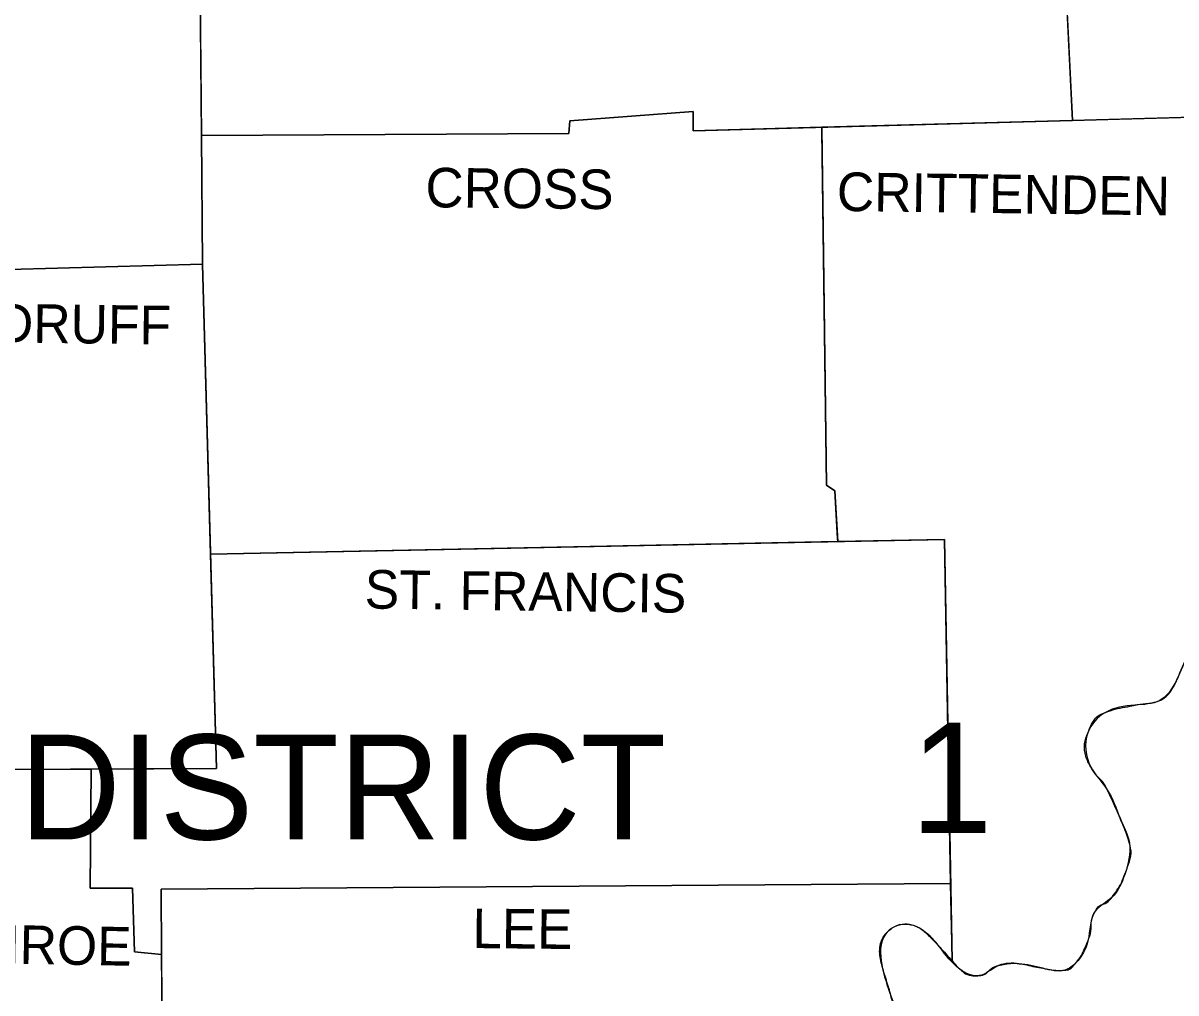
# Model space of a CAD drawing. Extents: x 185 to 5012, y 113 to 2127.
# Drawn here: x 3121.8 to 3244.3, y 1737.5 to 1840.7 of the extents above; entities that cross this region are included whole.
import ezdxf

# ---------------------------------------------------------------- set-up
doc = ezdxf.new("R2010")
doc.units = 0
doc.layers.add('Default', color=7, linetype='Continuous')
doc.layers.add('R_No Plot', color=7, linetype='Continuous')

msp = doc.modelspace()

# ---------------------------------------------------------------- linework, layer by layer
at = {"layer": 'Default'}
for points in [[(3094.0589629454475, 1986.3640190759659), (3093.688561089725, 1983.4007516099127), (3095.6453774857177, 1983.1072483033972), (3095.547585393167, 1981.9330851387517), (3097.797853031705, 1981.4438754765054), (3097.9935871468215, 1979.8784120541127), (3099.0698249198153, 1979.1934960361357), (3099.3633136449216, 1974.4970308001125), (3104.940236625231, 1973.9099492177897), (3104.940236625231, 1969.7026936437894), (3106.9948825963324, 1969.409152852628), (3106.9948825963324, 1967.7458549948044), (3108.7560398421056, 1967.2566453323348), (3108.6582102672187, 1961.5817232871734), (3110.2236333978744, 1961.2882199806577), (3110.615026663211, 1948.4707469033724), (3102.298538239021, 1947.687996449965), (3102.3963678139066, 1944.9483698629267), (3099.8524990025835, 1944.850572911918), (3100.7331151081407, 1894.3635060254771), (3140.162894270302, 1893.4829211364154), (3140.847776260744, 1815.0127317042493), (3115.1156743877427, 1814.3278156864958), (3114.604746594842, 1828.1237080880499)], [(3229.6643301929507, 1913.337334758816), (3231.3504033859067, 1870.3919701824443), (3233.3396171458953, 1830.3091142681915)], [(3140.7282791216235, 1828.704087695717), (3179.7883700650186, 1828.9064585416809), (3179.8862371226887, 1830.2762530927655), (3192.9968619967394, 1831.2546724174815), (3192.9968619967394, 1829.199999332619), (3251.279533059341, 1830.8023237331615)], [(3206.689650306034, 1829.5764455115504), (3207.1837621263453, 1791.5303680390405), (3208.064340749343, 1790.9433614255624), (3208.376644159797, 1785.5293148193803)], [(3206.6945392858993, 1829.199999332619), (3207.1837621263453, 1791.5303680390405), (3208.064340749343, 1790.9433614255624), (3208.3578294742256, 1785.8554834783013)], [(3206.6945392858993, 1829.199999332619), (3207.1837621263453, 1791.5303680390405), (3208.064340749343, 1790.9433614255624), (3208.3578294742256, 1785.8554834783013)], [(3206.6945392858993, 1829.199999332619), (3207.1837621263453, 1791.5303680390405), (3208.064340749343, 1790.9433614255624), (3208.3578294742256, 1785.8554834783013)], [(3206.6945392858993, 1829.199999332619), (3207.1837621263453, 1791.5303680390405), (3208.064340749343, 1790.9433614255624), (3208.3578294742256, 1785.8554834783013)], [(3140.847776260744, 1815.0127317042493), (3142.3154072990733, 1761.3947004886), (3119.029307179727, 1761.296866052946), (3118.931477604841, 1759.1443210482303), (3112.1804872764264, 1758.7529458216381), (3111.593397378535, 1747.598845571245), (3102.3153265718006, 1747.598845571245)], [(3141.6915784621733, 1784.1854927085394), (3219.707372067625, 1785.7576490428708)], [(3219.707372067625, 1785.7576490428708), (3220.490046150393, 1742.9023428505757)], [(3219.707372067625, 1785.7576490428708), (3220.490046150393, 1742.9023428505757)], [(3219.707372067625, 1785.7576490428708), (3220.490046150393, 1742.9023428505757)], [(3219.707372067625, 1785.7576490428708), (3220.490046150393, 1742.9023428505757)], [(3219.707372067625, 1785.7576490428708), (3220.490046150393, 1742.9023428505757)], [(3219.707372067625, 1785.7576490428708), (3220.490046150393, 1742.9023428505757)], [(3219.707372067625, 1785.7576490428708), (3220.490046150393, 1742.9023428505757)], [(3219.707372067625, 1785.7576490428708), (3220.5258742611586, 1740.9405752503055)], [(3129.0133703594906, 1761.3388131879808), (3128.9112187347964, 1748.6750993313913), (3133.411866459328, 1748.6750993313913), (3133.6076005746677, 1741.9239235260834), (3136.4970377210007, 1741.6249948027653)], [(3140.5253881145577, 1661.792305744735), (3149.653450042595, 1662.3774428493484), (3149.5555829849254, 1682.2395575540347), (3142.4132368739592, 1682.728842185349), (3142.8045926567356, 1721.572524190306), (3136.6406547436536, 1722.4531090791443), (3136.444958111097, 1748.5772648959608), (3220.375622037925, 1749.1676331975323)]]:
    msp.add_lwpolyline(points, dxfattribs=at)
msp.add_spline([(3256.2019266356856, 1822.4487860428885), (3256.5932824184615, 1819.6113625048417), (3254.929992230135, 1816.5782326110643), (3254.3429772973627, 1813.5451027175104), (3254.63646602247, 1810.5119353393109), (3251.505582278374, 1808.8485999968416), (3248.7660543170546, 1806.891761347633), (3250.33151493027, 1804.5435099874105), (3253.2667020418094, 1802.3909649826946), (3256.2019266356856, 1800.727667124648), (3258.0609134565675, 1799.0642942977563), (3258.550098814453, 1795.052707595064), (3259.0393216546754, 1792.508787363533), (3260.01772985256, 1788.9864478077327), (3260.409085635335, 1786.5403994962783), (3258.64792838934, 1783.6050665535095), (3256.5932824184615, 1783.0180224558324), (3254.4408068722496, 1783.7029009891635), (3251.896938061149, 1783.8986073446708), (3249.842292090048, 1781.9417686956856), (3248.374661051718, 1779.2021421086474), (3246.907067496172, 1776.462515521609), (3245.830829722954, 1774.114339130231), (3244.7545544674, 1771.5703814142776), (3242.602078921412, 1768.635048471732), (3239.9604180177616, 1768.145876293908), (3236.829459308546, 1767.3631258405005), (3234.9705099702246, 1765.210580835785), (3235.2640361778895, 1761.590369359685), (3237.0251559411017, 1759.1443210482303), (3238.394957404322, 1756.1111911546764), (3239.3733281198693, 1753.4693615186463), (3238.884105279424, 1750.1427283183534), (3237.5143787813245, 1747.696680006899), (3235.753184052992, 1746.2290135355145), (3234.9705099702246, 1743.0980492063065), (3233.6985755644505, 1740.7497978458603), (3232.524470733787, 1739.9670473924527), (3230.1762985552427, 1740.1627537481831), (3227.6324297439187, 1740.6519634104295), (3225.479954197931, 1740.4562195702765), (3223.4253082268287, 1739.37996581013), (3221.370662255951, 1740.0648818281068), (3219.2181867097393, 1742.4131331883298), (3217.4569919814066, 1744.174302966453), (3215.500213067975, 1744.8591814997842), (3213.445567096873, 1743.7829277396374), (3213.0542113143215, 1740.5541289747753), (3214.032619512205, 1737.22745829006), (3214.913160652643, 1732.7266994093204), (3214.032619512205, 1729.9870728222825), (3213.739093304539, 1725.486276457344)], degree=3, dxfattribs=at)
at = {"layer": 'R_No Plot'}
for p, q in [((3233.3396171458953, 1830.3091142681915), (3231.3504033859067, 1870.3919701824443)), ((3140.3825345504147, 1868.3176888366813), (3140.7282791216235, 1828.704087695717)), ((3233.3396171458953, 1830.3091142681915), (3251.279533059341, 1830.8023237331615)), ((3140.7282791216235, 1828.704087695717), (3140.847776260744, 1815.0127317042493)), ((3206.689650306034, 1829.5764455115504), (3206.6945392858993, 1829.199999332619)), ((3206.6945392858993, 1829.199999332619), (3206.689656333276, 1829.5759814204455)), ((3206.6945392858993, 1829.199999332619), (3207.1837621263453, 1791.5303680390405)), ((3207.1837621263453, 1791.5303680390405), (3206.6945392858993, 1829.199999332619)), ((3140.847776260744, 1815.0127317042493), (3141.6915784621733, 1784.1854927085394)), ((3141.6915784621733, 1784.1854927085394), (3140.847776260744, 1815.0127317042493)), ((3207.1837621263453, 1791.5303680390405), (3208.064340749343, 1790.9433614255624)), ((3208.064340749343, 1790.9433614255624), (3207.1837621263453, 1791.5303680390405)), ((3208.064340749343, 1790.9433614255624), (3208.3578294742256, 1785.8554834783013)), ((3208.3578294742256, 1785.8554834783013), (3208.064340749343, 1790.9433614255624)), ((3208.3578294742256, 1785.8554834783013), (3208.376644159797, 1785.5293148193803)), ((3208.376644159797, 1785.5293148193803), (3208.3578294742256, 1785.8554834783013)), ((3208.376644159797, 1785.5293148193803), (3219.707372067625, 1785.7576490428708)), ((3219.707372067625, 1785.7576490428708), (3208.376644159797, 1785.5293148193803)), ((3219.707372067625, 1785.7576490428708), (3220.375622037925, 1749.1676331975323)), ((3220.375622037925, 1749.1676331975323), (3219.707372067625, 1785.7576490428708)), ((3141.6915784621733, 1784.1854927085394), (3208.376644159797, 1785.5293148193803)), ((3208.376644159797, 1785.5293148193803), (3141.6915784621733, 1784.1854927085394)), ((3119.029307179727, 1761.296866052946), (3129.0133703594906, 1761.3388131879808)), ((3136.444958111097, 1748.5772648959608), (3220.375622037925, 1749.1676331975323)), ((3220.375622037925, 1749.1676331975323), (3136.444958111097, 1748.5772648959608)), ((3220.375622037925, 1749.1676331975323), (3220.490046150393, 1742.9023428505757)), ((3220.490046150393, 1742.9023428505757), (3220.375622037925, 1749.1676331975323)), ((3133.6076005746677, 1741.9239235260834), (3133.411866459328, 1748.6750993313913)), ((3136.4970377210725, 1741.6249948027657), (3136.444958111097, 1748.5772648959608)), ((3136.444958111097, 1748.5772648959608), (3136.4970377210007, 1741.6249948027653)), ((3220.490046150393, 1742.9023428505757), (3220.525838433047, 1740.9425370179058)), ((3220.525838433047, 1740.9425370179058), (3220.490046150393, 1742.9023428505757)), ((3136.4970377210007, 1741.6249948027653), (3133.6076005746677, 1741.9239235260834)), ((3136.6406547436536, 1722.4531090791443), (3136.4970377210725, 1741.6249948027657))]:
    msp.add_line(p, q, dxfattribs=at)
for points in [[(3229.6643301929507, 1913.337334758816), (3231.3504033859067, 1870.3919701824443), (3233.3396171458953, 1830.3091142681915)], [(3114.604746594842, 1828.1237080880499), (3115.1156743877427, 1814.3278156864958), (3140.847776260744, 1815.0127317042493), (3140.7282791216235, 1828.704087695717), (3140.3825345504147, 1868.3176888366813), (3140.162894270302, 1893.4829211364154), (3118.408442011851, 1893.9687631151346)], [(3140.7282791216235, 1828.704087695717), (3179.7883700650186, 1828.9064585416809), (3179.8862371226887, 1830.2762530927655), (3192.9968619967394, 1831.2546724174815), (3192.9968619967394, 1829.199999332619), (3233.3396171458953, 1830.3091142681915)], [(3206.689656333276, 1829.5759814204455), (3192.9968619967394, 1829.199999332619), (3192.9968619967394, 1831.2546724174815), (3179.8862371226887, 1830.2762530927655), (3179.7883700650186, 1828.9064585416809), (3140.7282791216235, 1828.704087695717)], [(3251.279533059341, 1830.8023237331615), (3233.3396171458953, 1830.3091142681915), (3206.689650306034, 1829.5764455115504)], [(3140.847776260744, 1815.0127317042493), (3115.1156743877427, 1814.3278156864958), (3114.604746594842, 1828.1237080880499)], [(3141.6915784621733, 1784.1854927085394), (3142.3154072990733, 1761.3947004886), (3129.0133703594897, 1761.3388131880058)], [(3129.0133703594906, 1761.3388131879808), (3142.3154072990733, 1761.3947004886), (3141.6915784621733, 1784.1854927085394)], [(3129.0133703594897, 1761.3388131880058), (3119.029307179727, 1761.296866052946), (3118.931477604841, 1759.1443210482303), (3112.1804872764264, 1758.7529458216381), (3111.593397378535, 1747.598845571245), (3102.3153265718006, 1747.598845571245)], [(3129.0133703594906, 1761.3388131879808), (3128.9112187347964, 1748.6750993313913), (3133.411866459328, 1748.6750993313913), (3133.6076005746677, 1741.9239235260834), (3136.4970377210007, 1741.6249948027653)], [(3133.411866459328, 1748.6750993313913), (3128.9112187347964, 1748.6750993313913), (3129.0133703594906, 1761.3388131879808)], [(3136.4970377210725, 1741.6249948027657), (3136.6406547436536, 1722.4531090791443), (3142.8045926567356, 1721.572524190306), (3142.6655133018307, 1707.7683223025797)]]:
    msp.add_lwpolyline(points, dxfattribs=at)
for points in [[(3240.2425872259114, 1768.1999793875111), (3241.429492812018, 1768.3472350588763), (3242.602078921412, 1768.635048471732), (3242.812692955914, 1768.7352942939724), (3243.0087024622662, 1768.8540067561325), (3243.360730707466, 1769.1405130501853), (3243.9315838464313, 1769.8656212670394), (3244.375803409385, 1770.7092763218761), (3244.7545544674, 1771.5703814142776), (3245.830829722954, 1774.114339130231), (3246.907067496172, 1776.462515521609), (3248.374661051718, 1779.2021421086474), (3249.842292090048, 1781.9417686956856), (3250.6979085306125, 1783.1128718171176), (3251.896938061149, 1783.8986073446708), (3252.20648179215, 1783.979966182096), (3252.5234271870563, 1784.0139990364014), (3253.169542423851, 1783.9742689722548), (3254.4408068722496, 1783.7029009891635), (3254.9792720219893, 1783.5454857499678), (3255.5172070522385, 1783.342286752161), (3256.0550608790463, 1783.1481752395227), (3256.5932824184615, 1783.0180224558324), (3257.1051577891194, 1782.9920623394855), (3257.6200225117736, 1783.0732863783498), (3258.1351786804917, 1783.2736394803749), (3258.64792838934, 1783.6050665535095), (3259.037938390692, 1783.9310898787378), (3259.3873295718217, 1784.2673658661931), (3259.9484272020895, 1784.973538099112), (3260.299564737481, 1785.7293077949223), (3260.409085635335, 1786.5403994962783), (3260.3687884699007, 1787.152558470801), (3260.2848176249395, 1787.7683222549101), (3260.01772985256, 1788.9864478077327), (3259.0393216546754, 1792.508787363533), (3258.7825012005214, 1793.778719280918), (3258.550098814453, 1795.052707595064), (3258.4352163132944, 1796.0534427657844), (3258.3861019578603, 1797.062911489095), (3258.2966896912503, 1798.0701749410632), (3258.0609134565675, 1799.0642942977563), (3257.9289517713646, 1799.3500748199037), (3257.7512770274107, 1799.6034627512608), (3257.2928363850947, 1800.0333552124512), (3256.2019266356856, 1800.727667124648), (3255.470261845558, 1801.1560882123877), (3254.7302890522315, 1801.5589169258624), (3253.9923289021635, 1801.9619452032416), (3253.2667020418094, 1802.3909649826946), (3251.774668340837, 1803.4103994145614), (3250.33151493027, 1804.5435099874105), (3249.085503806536, 1805.7170164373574), (3248.69986335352, 1806.3497453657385), (3248.7660543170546, 1806.891761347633), (3249.011365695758, 1807.163707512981), (3249.3045688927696, 1807.4244085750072), (3249.99436974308, 1807.9189419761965), (3250.7548948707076, 1808.3890947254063), (3251.505582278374, 1808.8485999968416), (3251.89638244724, 1809.05951843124), (3252.3056202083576, 1809.224269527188), (3253.1428534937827, 1809.505889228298), (3253.944172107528, 1809.874698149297), (3254.63646602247, 1810.5119353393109), (3254.7476282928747, 1810.6921212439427), (3254.820501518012, 1810.874978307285), (3254.869399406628, 1811.2474891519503), (3254.7059309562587, 1812.0111804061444), (3254.434357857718, 1812.7835409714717), (3254.3429772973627, 1813.5451027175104), (3254.5755914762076, 1815.0668578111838), (3254.929992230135, 1816.5782326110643), (3255.2966779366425, 1817.3727806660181), (3255.802428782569, 1818.1103934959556), (3256.2877838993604, 1818.840208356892), (3256.5932824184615, 1819.6113625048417), (3256.2019266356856, 1822.4487860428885)], [(3213.739093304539, 1725.486276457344), (3214.032619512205, 1729.9870728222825), (3214.2087299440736, 1730.6870722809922), (3214.5206578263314, 1731.3655456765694), (3214.8087018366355, 1732.0396892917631), (3214.913160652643, 1732.7266994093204), (3214.865740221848, 1733.2857583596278), (3214.7912032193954, 1733.8479601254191), (3214.5792142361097, 1734.977526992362), (3214.032619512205, 1737.22745829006), (3213.8007740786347, 1738.0646230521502), (3213.5424997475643, 1738.8952942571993), (3213.2846832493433, 1739.7237151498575), (3213.0542113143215, 1740.5541289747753), (3212.831504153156, 1742.164170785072), (3212.9868378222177, 1742.9805938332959), (3213.445567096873, 1743.7829277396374), (3213.679583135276, 1744.044810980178), (3213.9229515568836, 1744.2679383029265), (3214.432077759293, 1744.6026647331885), (3215.500213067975, 1744.8591814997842), (3216.0003393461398, 1744.8195976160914), (3216.5148566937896, 1744.6964689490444), (3217.0112469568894, 1744.4834769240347), (3217.4569919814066, 1744.174302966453), (3218.368010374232, 1743.302417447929), (3219.2181867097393, 1742.4131331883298), (3220.525838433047, 1740.9425370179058)]]:
    msp.add_spline(points, degree=3, dxfattribs=at)
msp.add_open_spline([(3220.525838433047, 1740.9425370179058), (3220.7898464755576, 1740.6464779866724), (3221.0654223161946, 1740.35216375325), (3221.370662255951, 1740.0648818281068), (3221.924145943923, 1739.5439609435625), (3222.7727591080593, 1739.309786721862), (3223.4253082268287, 1739.37996581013), (3224.1241512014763, 1739.4551236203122), (3224.725381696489, 1740.310066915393), (3225.479954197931, 1740.4562195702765), (3226.1830998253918, 1740.5924113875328), (3226.9237729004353, 1740.7435822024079), (3227.6324297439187, 1740.6519634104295), (3228.4817847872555, 1740.5421544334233), (3229.327365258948, 1740.297994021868), (3230.1762985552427, 1740.1627537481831), (3230.948493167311, 1740.0397384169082), (3231.746818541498, 1739.9091559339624), (3232.524470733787, 1739.9670473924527), (3232.9901699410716, 1740.0017158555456), (3233.37632225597, 1740.355234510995), (3233.6985755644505, 1740.7497978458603), (3234.3084443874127, 1741.4965143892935), (3234.6305172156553, 1742.2751901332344), (3234.9705099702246, 1743.0980492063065), (3235.3813735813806, 1744.0924317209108), (3235.234796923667, 1745.2851514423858), (3235.753184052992, 1746.2290135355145), (3236.121437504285, 1746.8995172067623), (3237.0566133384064, 1747.0763358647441), (3237.5143787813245, 1747.696680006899), (3238.0741439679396, 1748.4552498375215), (3238.5435936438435, 1749.2380268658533), (3238.884105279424, 1750.1427283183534), (3239.29250592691, 1751.2278033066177), (3239.67539548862, 1752.4076667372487), (3239.3733281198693, 1753.4693615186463), (3239.1202418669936, 1754.3588993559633), (3238.7657911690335, 1755.2390259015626), (3238.394957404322, 1756.1111911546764), (3237.9568681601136, 1757.1415348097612), (3237.5034535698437, 1758.1470914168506), (3237.0251559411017, 1759.1443210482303), (3236.5919832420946, 1760.0474671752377), (3235.754768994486, 1760.7203405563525), (3235.2640361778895, 1761.590369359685), (3234.672693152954, 1762.6387717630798), (3234.522409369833, 1764.080747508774), (3234.9705099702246, 1765.210580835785), (3235.321406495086, 1766.0953254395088), (3235.915017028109, 1767.0350561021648), (3236.829459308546, 1767.3631258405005), (3237.8671270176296, 1767.735404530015), (3238.9104492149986, 1767.914336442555), (3239.9604180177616, 1768.145876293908), (3240.0541125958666, 1768.1665378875), (3240.148203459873, 1768.1842977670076), (3240.2425872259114, 1768.1999793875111)], degree=3, dxfattribs=at)

# ---------------------------------------------------------------- texts
at = {"layer": 'Default'}
for s, height, rotation, p in [('CROSS', 4.206862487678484, 359.383922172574, (3164.525232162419, 1821.0789914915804)), ('CRITTENDEN', 4.109939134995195, 359.2129997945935, (3208.259999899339, 1820.6876162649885)), ('WOODRUFF', 4.108700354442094, 359.2747556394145, (3105.1359332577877, 1806.891761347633)), ('ST. FRANCIS', 4.108764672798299, 359.22155299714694, (3158.0677305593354, 1778.4193916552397)), ('LEE', 4.207919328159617, 359.43271626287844, (3169.5151027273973, 1742.3152987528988)), ('MONROE', 4.108764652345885, 359.03305196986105, (3108.560343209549, 1740.8476322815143))]:
    msp.add_text(s, height=height, rotation=rotation, dxfattribs=at).set_placement(p)
for s, height, p in [('1', 11.741051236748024, (3216.087265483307, 1754.5456527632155)), ('DISTRICT', 11.153992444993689, (3121.377516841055, 1753.8607742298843))]:
    msp.add_text(s, height=height, dxfattribs=at).set_placement(p)

doc.saveas('drawing.dxf')
